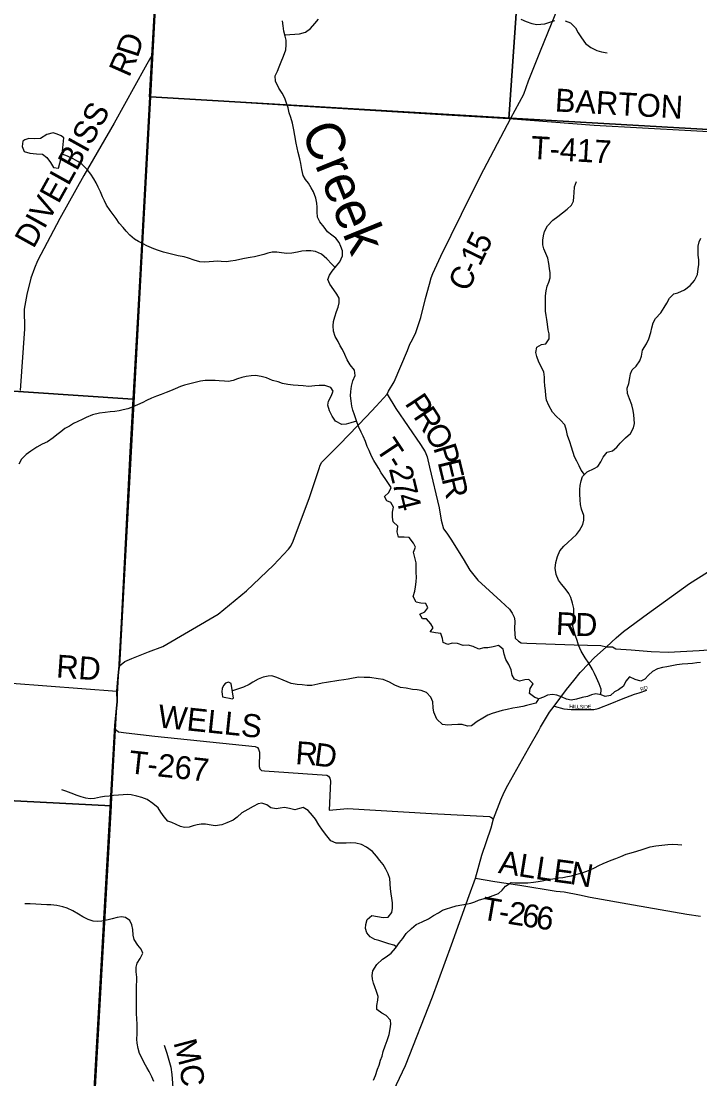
# Model space of a CAD drawing. Extents: x 1759416 to 2214760, y 252598 to 1116833.
# Drawn here: x 1977423 to 1986288, y 885483 to 899295 of the extents above; entities that cross this region are included whole.
import ezdxf

# ---------------------------------------------------------------- set-up
doc = ezdxf.new("R2010")
doc.units = 0
for name, color, linetype in [('GM_X_County_Road', 7, 'Continuous'), ('GM_X_County_Road_Text', 7, 'Continuous'), ('GM_X_Minor_Lake', 7, 'Continuous'), ('GM_X_Minor_River', 7, 'Continuous'), ('GM_X_Minor_River_Text', 7, 'Continuous'), ('GM_X_Section', 7, 'Continuous'), ('GM_X_State_Route', 7, 'Continuous'), ('GM_X_Township', 7, 'Continuous'), ('GM_X_Township_Road', 7, 'Continuous'), ('GM_X_Township_Road_Text', 7, 'Continuous'), ('GM_X_Township_Subdivision', 7, 'Continuous'), ('GM_X_Township_Subdivision_Text', 7, 'Continuous')]:
    doc.layers.add(name, color=color, linetype=linetype)

msp = doc.modelspace()

# ---------------------------------------------------------------- linework, layer by layer
at = {"layer": 'GM_X_County_Road'}
for points in [[(1983819, 898028), (1983988, 898340), (1984048, 898516), (1984207, 898906), (1984400, 899379), (1984779, 900247), (1984893, 900512), (1984969, 900674)], [(1978703, 890857), (1978707, 890875), (1978778, 890932), (1978869, 890972), (1979088, 891058), (1979274, 891129), (1979996, 891552), (1980365, 891854), (1980721, 892190), (1980914, 892400), (1980948, 892438), (1980976, 892505), (1981189, 893075), (1981315, 893454), (1981329, 893498), (1981351, 893534), (1981584, 893772), (1981932, 894130), (1982061, 894266), (1982203, 894422), (1982221, 894462), (1982297, 894586), (1982468, 894993), (1982502, 895077), (1982536, 895137), (1982578, 895229), (1982642, 895423), (1982706, 895671), (1982757, 895859), (1982779, 895944), (1982799, 896000), (1982905, 896226), (1983174, 896776), (1983425, 897273), (1983819, 898028)], [(1972514, 887236), (1972538, 887251), (1972709, 887356), (1973825, 888105), (1974073, 888287), (1974650, 888727), (1975449, 889323), (1976258, 889912), (1976731, 890268), (1976773, 890314), (1976797, 890358), (1976815, 890434), (1976839, 890684), (1978673, 890545), (1978688, 890708), (1978698, 890834), (1978703, 890857)]]:
    msp.add_lwpolyline(points, dxfattribs=at)
at = {"layer": 'GM_X_Minor_Lake'}
for points in [[(1977983, 897770), (1977947, 897796), (1977895, 897821), (1977843, 897837), (1977759, 897815), (1977674, 897764), (1977598, 897760), (1977524, 897761), (1977470, 897747), (1977444, 897727), (1977436, 897657), (1977463, 897593), (1977535, 897570), (1977623, 897564), (1977701, 897557), (1977761, 897515), (1977805, 897451), (1977844, 897382), (1977910, 897374)], [(1977910, 897374), (1977959, 897552), (1977983, 897770)], [(1980168, 890646), (1980130, 890662), (1980094, 890649), (1980068, 890619), (1980049, 890581), (1980045, 890535), (1980047, 890505), (1980053, 890473), (1980099, 890464), (1980145, 890454), (1980179, 890446), (1980199, 890456)], [(1980199, 890456), (1980168, 890646)]]:
    msp.add_lwpolyline(points, dxfattribs=at)
at = {"layer": 'GM_X_Minor_River'}
for points in [[(1980866, 899117), (1980996, 899123), (1981060, 899131), (1981139, 899152), (1981203, 899198), (1981261, 899263), (1981308, 899321)], [(1982289, 892946), (1982253, 893007), (1982199, 893031), (1982171, 893089), (1982224, 893139), (1982258, 893203), (1982213, 893270), (1982177, 893322), (1982127, 893398), (1982096, 893453), (1982066, 893503), (1982032, 893557), (1981998, 893615), (1981967, 893690), (1981945, 893742), (1981922, 893804), (1981892, 893875), (1981864, 893929), (1981835, 893993), (1981811, 894049), (1981793, 894100), (1981776, 894152), (1981756, 894214), (1981744, 894268), (1981733, 894338), (1981727, 894400), (1981728, 894459), (1981738, 894527), (1981754, 894597), (1981787, 894667), (1981779, 894735), (1981720, 894805), (1981680, 894872), (1981653, 894940), (1981619, 895006), (1981591, 895056), (1981564, 895111), (1981526, 895177), (1981504, 895245), (1981499, 895315), (1981505, 895372), (1981520, 895432), (1981544, 895503), (1981564, 895561), (1981577, 895615), (1981575, 895678), (1981545, 895728), (1981506, 895788), (1981454, 895859), (1981431, 895921), (1981453, 895977), (1981485, 896031), (1981544, 896100), (1981586, 896152), (1981621, 896230), (1981619, 896296), (1981601, 896353), (1981576, 896405), (1981532, 896459), (1981480, 896498), (1981426, 896542), (1981381, 896606), (1981323, 896673), (1981296, 896735), (1981290, 896803), (1981288, 896865), (1981285, 896919), (1981271, 896982), (1981240, 897068), (1981210, 897120), (1981176, 897177), (1981138, 897229), (1981107, 897279), (1981091, 897357), (1981078, 897434), (1981064, 897496), (1981043, 897578), (1981029, 897640), (1981015, 897700), (1980998, 897801), (1980984, 897875), (1980967, 897961), (1980945, 898037), (1980926, 898098), (1980910, 898162), (1980894, 898212), (1980869, 898288), (1980831, 898355), (1980790, 898421), (1980744, 898512), (1980743, 898582), (1980773, 898640), (1980793, 898698), (1980820, 898763), (1980848, 898837), (1980879, 898921), (1980887, 898985), (1980884, 899048), (1980870, 899098), (1980856, 899162), (1980847, 899232)], [(1980847, 899232), (1980837, 899300)], [(1983950, 899320), (1984020, 899292), (1984094, 899263), (1984160, 899253), (1984210, 899255), (1984264, 899262), (1984341, 899286), (1984393, 899302)], [(1984529, 899301), (1984597, 899274), (1984664, 899208), (1984700, 899141), (1984742, 899077), (1984795, 899004), (1984863, 898950), (1984943, 898913), (1985005, 898893), (1985077, 898882)], [(1981525, 896078), (1981482, 896123), (1981418, 896189), (1981347, 896252), (1981267, 896285), (1981209, 896297), (1981147, 896295), (1981091, 896290), (1981034, 896278), (1980960, 896266), (1980894, 896261), (1980826, 896269), (1980764, 896280), (1980704, 896280), (1980646, 896264), (1980592, 896249), (1980471, 896218), (1980413, 896210), (1980341, 896196), (1980281, 896183), (1980225, 896171), (1980157, 896159), (1980105, 896154), (1980037, 896156), (1979985, 896159), (1979935, 896157), (1979880, 896153), (1979820, 896148), (1979758, 896150), (1979684, 896172), (1979610, 896199), (1979551, 896217), (1979473, 896232), (1979403, 896246), (1979351, 896259), (1979281, 896279), (1979219, 896300), (1979155, 896322), (1979067, 896359), (1979015, 896385), (1978957, 896418), (1978903, 896448), (1978844, 896500), (1978796, 896551), (1978754, 896601), (1978705, 896658), (1978663, 896718), (1978625, 896772), (1978587, 896823), (1978540, 896893), (1978512, 896947), (1978488, 896999), (1978459, 897068), (1978429, 897126), (1978402, 897182), (1978372, 897235), (1978334, 897297), (1978285, 897359), (1978217, 897426), (1978165, 897460), (1978101, 897499), (1978027, 897531), (1977960, 897556)], [(1984782, 893374), (1984738, 893432), (1984710, 893488), (1984681, 893550), (1984651, 893604), (1984610, 893731), (1984592, 893801), (1984559, 893886), (1984545, 893950), (1984524, 894022), (1984468, 894084), (1984410, 894137), (1984364, 894189), (1984317, 894274), (1984287, 894346), (1984278, 894408), (1984272, 894472), (1984262, 894532), (1984257, 894595), (1984257, 894647), (1984250, 894715), (1984186, 894843), (1984161, 894916), (1984145, 894970), (1984160, 895038), (1984222, 895074), (1984278, 895083), (1984318, 895147), (1984321, 895211), (1984309, 895265), (1984300, 895340), (1984290, 895400), (1984280, 895450), (1984273, 895506), (1984271, 895564), (1984270, 895644), (1984270, 895708), (1984280, 895772), (1984295, 895832), (1984317, 895888), (1984331, 895944), (1984332, 896008), (1984326, 896065), (1984317, 896131), (1984303, 896199), (1984275, 896259), (1984252, 896320), (1984238, 896372), (1984239, 896434), (1984247, 896492), (1984261, 896550), (1984298, 896622), (1984368, 896695), (1984433, 896743), (1984493, 896793), (1984555, 896838), (1984612, 896890), (1984636, 896944), (1984642, 897002), (1984645, 897054), (1984653, 897130), (1984678, 897200)], [(1984996, 890498), (1985000, 890573), (1984971, 890642), (1984939, 890720), (1984913, 890774), (1984888, 890830), (1984838, 890911), (1984791, 890981), (1984739, 891066), (1984705, 891144), (1984686, 891206), (1984662, 891269), (1984647, 891323), (1984633, 891373), (1984627, 891439), (1984636, 891491), (1984642, 891545), (1984642, 891625), (1984625, 891694), (1984601, 891768), (1984576, 891820), (1984528, 891884), (1984480, 891943), (1984441, 891993), (1984413, 892069), (1984400, 892152), (1984406, 892226), (1984431, 892304), (1984459, 892376), (1984511, 892437), (1984566, 892487), (1984622, 892541), (1984679, 892593), (1984715, 892644), (1984758, 892722), (1984772, 892780), (1984772, 892838), (1984743, 892921), (1984729, 892985), (1984724, 893043), (1984720, 893119), (1984720, 893177), (1984725, 893233), (1984737, 893291), (1984755, 893347), (1984818, 893411), (1984906, 893455), (1984957, 893480), (1984997, 893540), (1985025, 893602), (1985078, 893668), (1985146, 893685), (1985204, 893731), (1985249, 893783), (1985319, 893853), (1985382, 893910), (1985422, 893986), (1985433, 894040), (1985429, 894098), (1985427, 894156), (1985416, 894211), (1985398, 894285), (1985371, 894363), (1985343, 894433), (1985339, 894504), (1985362, 894562), (1985374, 894636), (1985381, 894690), (1985405, 894742), (1985455, 894789), (1985504, 894857), (1985524, 894919), (1985541, 894997), (1985591, 895079), (1985624, 895147), (1985650, 895229), (1985661, 895291), (1985679, 895357), (1985707, 895413), (1985778, 895486), (1985822, 895554), (1985859, 895614), (1985893, 895676), (1985950, 895732), (1986002, 895749), (1986086, 895785), (1986161, 895841), (1986217, 895910), (1986258, 895986), (1986268, 896060), (1986275, 896118), (1986275, 896180), (1986265, 896240), (1986268, 896297), (1986268, 896357), (1986280, 896411), (1986303, 896463)], [(1981803, 894073), (1981729, 894050), (1981667, 894032), (1981611, 894029), (1981529, 894073), (1981485, 894138), (1981452, 894204), (1981430, 894278), (1981440, 894334), (1981473, 894396), (1981497, 894462), (1981470, 894512), (1981390, 894537), (1981318, 894539), (1981258, 894534), (1981179, 894524), (1981107, 894531), (1981043, 894535), (1980975, 894542), (1980907, 894550), (1980837, 894564), (1980781, 894583), (1980707, 894603), (1980630, 894636), (1980558, 894654), (1980486, 894669), (1980426, 894665), (1980363, 894656), (1980305, 894640), (1980251, 894622), (1980193, 894603), (1980133, 894591), (1980079, 894595), (1980011, 894600), (1979959, 894604), (1979901, 894604), (1979825, 894603), (1979767, 894595), (1979680, 894570), (1979608, 894556), (1979558, 894543), (1979506, 894523), (1979434, 894493), (1979373, 894468), (1979317, 894446), (1979253, 894420), (1979193, 894397), (1979126, 894371), (1979062, 894341), (1979012, 894316), (1978944, 894284), (1978873, 894254), (1978815, 894231), (1978757, 894217), (1978705, 894205), (1978649, 894198), (1978587, 894192), (1978519, 894185), (1978447, 894177), (1978354, 894152), (1978274, 894120), (1978220, 894094), (1978162, 894067), (1978107, 894039), (1978055, 894005), (1977995, 893974), (1977943, 893934), (1977890, 893892), (1977840, 893852), (1977766, 893803), (1977697, 893769), (1977629, 893730), (1977549, 893680), (1977488, 893636), (1977428, 893577), (1977393, 893511)], [(1986298, 890918), (1986248, 890914), (1986191, 890908), (1986131, 890903), (1986059, 890897), (1985989, 890887), (1985923, 890878), (1985855, 890864), (1985799, 890855), (1985733, 890835), (1985668, 890801), (1985618, 890754), (1985570, 890702), (1985517, 890676), (1985445, 890699), (1985368, 890731), (1985323, 890677), (1985293, 890609), (1985224, 890564), (1985174, 890536), (1985120, 890488), (1985052, 890475), (1984998, 890497), (1984930, 890512), (1984872, 890498), (1984819, 890474), (1984751, 890461), (1984675, 890439), (1984609, 890426), (1984545, 890440), (1984489, 890468), (1984419, 890493), (1984365, 890503), (1984297, 890492), (1984247, 890466), (1984187, 890444), (1984133, 890461), (1984063, 890513), (1984073, 890579), (1984110, 890643), (1984054, 890696), (1984002, 890692), (1983932, 890676), (1983866, 890701), (1983838, 890753), (1983823, 890825), (1983793, 890893), (1983755, 890960), (1983732, 891030), (1983718, 891092), (1983658, 891141), (1983590, 891125), (1983518, 891112), (1983468, 891112), (1983402, 891092), (1983326, 891129), (1983264, 891145), (1983196, 891140), (1983122, 891166), (1983054, 891171), (1982998, 891153), (1982934, 891181), (1982926, 891234), (1982905, 891300), (1982835, 891306), (1982767, 891319), (1982807, 891373), (1982775, 891425), (1982716, 891489), (1982666, 891488), (1982630, 891552), (1982696, 891582), (1982737, 891635), (1982707, 891692), (1982645, 891694), (1982581, 891707), (1982545, 891781), (1982564, 891853), (1982576, 891907), (1982583, 891975), (1982587, 892033), (1982585, 892093), (1982584, 892149), (1982582, 892219), (1982565, 892290), (1982547, 892362), (1982576, 892426), (1982548, 892480), (1982492, 892551), (1982424, 892555), (1982354, 892557), (1982333, 892626), (1982345, 892698), (1982283, 892756), (1982274, 892818), (1982274, 892882), (1982289, 892946)], [(1984179, 890446), (1984144, 890390), (1984092, 890377), (1984026, 890359), (1983974, 890347), (1983904, 890330), (1983847, 890322), (1983773, 890307), (1983705, 890293), (1983575, 890254), (1983521, 890232), (1983452, 890193), (1983380, 890147), (1983307, 890091), (1983255, 890090), (1983183, 890110), (1983125, 890110), (1983049, 890105), (1982997, 890101), (1982925, 890110), (1982852, 890178), (1982814, 890271), (1982804, 890327), (1982799, 890405), (1982775, 890467), (1982718, 890530), (1982648, 890554), (1982596, 890563), (1982534, 890569), (1982452, 890584), (1982380, 890594), (1982304, 890625), (1982236, 890661), (1982150, 890696), (1982086, 890706), (1981978, 890723), (1981902, 890725), (1981832, 890726), (1981760, 890714), (1981696, 890703), (1981636, 890693), (1981572, 890683), (1981519, 890676), (1981463, 890668), (1981411, 890658), (1981355, 890649), (1981299, 890635), (1981219, 890621), (1981161, 890620), (1981093, 890626), (1981027, 890631), (1980951, 890647), (1980897, 890666), (1980845, 890688), (1980763, 890723), (1980699, 890745), (1980649, 890741), (1980583, 890728), (1980521, 890700), (1980450, 890662), (1980400, 890633), (1980326, 890599), (1980264, 890576), (1980184, 890548)], [(1982327, 887208), (1982290, 887229), (1982226, 887245), (1982160, 887268), (1982097, 887288), (1982045, 887303), (1981983, 887339), (1981939, 887390), (1981923, 887448), (1981926, 887498), (1981942, 887562), (1982005, 887614), (1982079, 887603), (1982151, 887589), (1982215, 887592), (1982263, 887654), (1982273, 887710), (1982272, 887780), (1982264, 887840), (1982255, 887900), (1982249, 887963), (1982238, 888099), (1982216, 888159), (1982187, 888221), (1982153, 888280), (1982107, 888334), (1982066, 888390), (1982012, 888451), (1981932, 888509), (1981868, 888544), (1981796, 888562), (1981722, 888563), (1981668, 888559), (1981608, 888560), (1981536, 888562), (1981468, 888589), (1981417, 888655), (1981361, 888729), (1981311, 888798), (1981266, 888872), (1981230, 888923), (1981174, 888989), (1981109, 889026), (1981058, 889014), (1980996, 888994), (1980928, 889013), (1980864, 889025), (1980806, 889017), (1980756, 889008), (1980686, 889022), (1980634, 889061), (1980568, 889081), (1980518, 889073), (1980452, 889038), (1980386, 889000), (1980307, 888957), (1980243, 888901), (1980193, 888861), (1980110, 888826), (1980044, 888800), (1979958, 888786), (1979904, 888795), (1979832, 888807), (1979776, 888810), (1979722, 888800), (1979670, 888786), (1979618, 888769), (1979557, 888763), (1979506, 888779), (1979450, 888804), (1979392, 888830), (1979340, 888849), (1979292, 888905), (1979248, 888963), (1979211, 889020), (1979145, 889080), (1979069, 889129), (1978999, 889155), (1978933, 889172), (1978859, 889190), (1978807, 889195), (1978755, 889193), (1978697, 889189), (1978629, 889182), (1978571, 889176), (1978511, 889168), (1978459, 889159), (1978383, 889145), (1978325, 889140), (1978267, 889148), (1978209, 889164), (1978157, 889183), (1978077, 889213), (1978005, 889240), (1977953, 889258)], [(1985132, 888339), (1985192, 888362), (1985255, 888384), (1985325, 888416), (1985393, 888435), (1985467, 888457), (1985533, 888476), (1985588, 888496), (1985638, 888512), (1985714, 888525), (1985792, 888535), (1985870, 888542), (1985932, 888546), (1986000, 888544), (1986052, 888539)], [(1982027, 885464), (1982053, 885526), (1982080, 885608), (1982100, 885660), (1982117, 885726), (1982137, 885778), (1982153, 885838), (1982180, 885914), (1982204, 885984), (1982229, 886062), (1982245, 886136), (1982252, 886196), (1982248, 886248), (1982190, 886310), (1982135, 886339), (1982067, 886387), (1982067, 886441), (1982082, 886509), (1982086, 886559), (1982066, 886625), (1982041, 886682), (1982027, 886734), (1982013, 886784), (1982008, 886834), (1982016, 886892), (1982069, 886974), (1982141, 887044), (1982191, 887077), (1982258, 887125), (1982314, 887191), (1982367, 887263), (1982407, 887316), (1982451, 887380), (1982520, 887444), (1982582, 887496), (1982661, 887535), (1982743, 887573), (1982809, 887616), (1982874, 887652), (1982926, 887686), (1982978, 887701), (1983034, 887719), (1983106, 887741), (1983179, 887756), (1983231, 887764), (1983295, 887778), (1983347, 887793), (1983399, 887817), (1983469, 887837), (1983521, 887850), (1983658, 887905), (1983708, 887947), (1983751, 887999), (1983823, 888045), (1983873, 888044), (1983927, 888042), (1983989, 888042), (1984041, 888043), (1984115, 888049), (1984175, 888060), (1984230, 888070), (1984312, 888084), (1984396, 888097), (1984448, 888107), (1984498, 888112), (1984558, 888124), (1984612, 888134), (1984666, 888151), (1984751, 888175), (1984801, 888191), (1984855, 888212), (1984911, 888238), (1984968, 888268), (1985024, 888293), (1985078, 888317), (1985132, 888339)], [(1978735, 887598), (1978677, 887591), (1978613, 887573), (1978561, 887559), (1978479, 887542), (1978427, 887536), (1978365, 887541), (1978297, 887563), (1978227, 887600), (1978171, 887632), (1978097, 887675), (1978023, 887713), (1977969, 887731), (1977889, 887746), (1977813, 887754), (1977759, 887757), (1977683, 887759), (1977615, 887764), (1977543, 887766), (1977473, 887769)], [(1979156, 885450), (1979130, 885510), (1979095, 885577), (1979067, 885629), (1979030, 885693), (1978994, 885764), (1978968, 885814), (1978951, 885878), (1978937, 885948), (1978933, 886000), (1978940, 886071), (1978940, 886139), (1978939, 886195), (1978935, 886267), (1978930, 886337), (1978928, 886407), (1978928, 886463), (1978931, 886513), (1978929, 886595), (1978932, 886656), (1978932, 886706), (1978934, 886756), (1978933, 886812), (1978927, 886882), (1978925, 886942), (1978940, 886994), (1978976, 887052), (1979011, 887124), (1978991, 887178), (1978949, 887230), (1978900, 887301), (1978886, 887361), (1978880, 887431), (1978867, 887495), (1978841, 887552), (1978787, 887588), (1978735, 887598)]]:
    msp.add_lwpolyline(points, dxfattribs=at)
at = {"layer": 'GM_X_Section'}
for points in [[(1984176, 903528), (1983794, 898018), (1982978, 898066), (1981055, 898186), (1979098, 898305), (1979185, 899839), (1979392, 903857)], [(1989634, 903190), (1989270, 897688), (1988740, 897714), (1986801, 897826), (1984910, 897934), (1983794, 898018), (1984176, 903528)], [(1979185, 899839), (1979098, 898305), (1978969, 895901), (1978883, 894359), (1973427, 894726), (1973703, 900155)], [(1978883, 894359), (1978845, 893672), (1978729, 891445), (1978603, 889173), (1978599, 889048), (1973201, 889326), (1973427, 894726)], [(1973201, 889326), (1978599, 889048), (1978479, 886916), (1978370, 884986), (1978281, 883552), (1972879, 883916)]]:
    msp.add_lwpolyline(points, close=True, dxfattribs=at)
at = {"layer": 'GM_X_State_Route'}
for points in [[(1985070, 891125), (1985197, 891242), (1985292, 891324), (1985603, 891553), (1986152, 891953), (1986507, 892172)], [(1984189, 890041), (1984208, 890075), (1984324, 890269), (1984386, 890349), (1984546, 890566), (1984641, 890686), (1984726, 890790), (1984838, 890905), (1984910, 890981), (1985070, 891125)], [(1981096, 883453), (1981250, 883656), (1981572, 884101), (1981789, 884419), (1981995, 884755), (1982009, 884782), (1982163, 885071), (1982443, 885656), (1982796, 886554), (1983044, 887232), (1983277, 887878), (1983358, 888104), (1983440, 888403), (1983564, 888762), (1983595, 888877), (1983687, 889125), (1983733, 889226), (1983782, 889319), (1984056, 889807), (1984189, 890041)]]:
    msp.add_lwpolyline(points, dxfattribs=at)
at = {"layer": 'GM_X_Township'}
for points in [[(1999329, 897063), (1998108, 897126), (1994987, 897287), (1993785, 897363), (1989453, 897682), (1987762, 897801), (1983819, 898028), (1979115, 898305), (1979144, 898890), (1979148, 898965), (1979181, 899629), (1979253, 901083), (1979280, 901405), (1979291, 901555), (1979302, 901673), (1979490, 905682), (1979566, 907131), (1979748, 910072), (1979980, 914711), (1980054, 916429)], [(1975033, 905927), (1979490, 905682), (1979302, 901673), (1979291, 901555), (1979280, 901405), (1979253, 901083), (1979181, 899629), (1979148, 898965), (1979144, 898890), (1979115, 898305), (1978707, 890875), (1978698, 890834), (1978688, 890708), (1978673, 890545), (1978676, 890411), (1978648, 890099), (1978275, 883589)], [(1978275, 883589), (1978648, 890099), (1978676, 890411), (1978673, 890545), (1978688, 890708), (1978698, 890834), (1978707, 890875), (1979115, 898305), (1983819, 898028), (1987762, 897801), (1989453, 897682), (1993785, 897363), (1994987, 897287), (1998108, 897126), (1999329, 897063)]]:
    msp.add_lwpolyline(points, dxfattribs=at)
at = {"layer": 'GM_X_Township_Road'}
for points in [[(1979253, 901083), (1979253, 901083), (1979181, 899629), (1979148, 898965), (1979144, 898890), (1979121, 898828), (1979106, 898801)], [(1979106, 898801), (1979045, 898692), (1978637, 897961), (1978241, 897280), (1977928, 896719), (1977638, 896164), (1977598, 896068), (1977551, 895940), (1977496, 895726), (1977463, 895534), (1977468, 895279), (1977411, 894470)], [(1983819, 898028), (1987762, 897801)], [(1982203, 894422), (1982319, 894238), (1982640, 893767), (1982672, 893719), (1982700, 893671), (1982725, 893604), (1982759, 893470), (1982883, 892938), (1982908, 892778), (1982939, 892665), (1982984, 892608), (1983035, 892531), (1983198, 892272), (1983283, 892127), (1983388, 891993), (1983690, 891721), (1983801, 891614), (1983837, 891563), (1983863, 891511), (1983872, 891465), (1983869, 891355), (1983878, 891238), (1983920, 891198), (1983956, 891178), (1984027, 891174), (1984648, 891151), (1984993, 891141), (1985070, 891125)], [(1985070, 891125), (1985147, 891124), (1985192, 891100), (1985392, 891084), (1985651, 891065), (1985873, 891055), (1986278, 891075), (1986468, 891088)], [(1978673, 890545), (1978676, 890411), (1978648, 890099), (1978657, 890044), (1978667, 890036)], [(1978667, 890036), (1978693, 890015), (1978793, 889999), (1979171, 889956), (1980479, 889822), (1980509, 889808), (1980525, 889787), (1980537, 889749), (1980532, 889561), (1980542, 889533), (1980562, 889511), (1980600, 889503), (1981414, 889448), (1981438, 889436), (1981456, 889408), (1981464, 889370), (1981445, 888991), (1981688, 889011), (1982781, 888949), (1983541, 888908), (1983560, 888901), (1983595, 888877)], [(1983358, 888104), (1983609, 888058), (1983936, 888010), (1984410, 887932), (1984517, 887923), (1984715, 887884), (1984857, 887857), (1985423, 887755), (1986118, 887633), (1986295, 887609)], [(1979291, 885921), (1979325, 885819), (1979378, 885634), (1979393, 885538), (1979408, 885308), (1979410, 884961), (1979418, 884931), (1979446, 884901), (1979508, 884885), (1980408, 884868), (1981391, 884806), (1981866, 884762), (1981995, 884755)]]:
    msp.add_lwpolyline(points, dxfattribs=at)
at = {"layer": 'GM_X_Township_Subdivision'}
for points in [[(1984386, 890349), (1984511, 890313), (1984607, 890308), (1984818, 890305), (1984903, 890308), (1984959, 890319), (1985140, 890388), (1985265, 890439), (1985436, 890505), (1985497, 890525)], [(1985497, 890525), (1985597, 890558)]]:
    msp.add_lwpolyline(points, dxfattribs=at)

# ---------------------------------------------------------------- texts
at = {"layer": 'GM_X_County_Road_Text'}
for s, rotation, p in [('5', 63.9214, (1983495, 896247)), ('1', 64.2239, (1983415, 896081)), ('C', 65.7867, (1983262, 895747)), ('-', 64.7685, (1983363, 895970)), ('RD', 356.0551, (1977875, 890724))]:
    msp.add_text(s, height=300, rotation=rotation, dxfattribs=at).set_placement(p)
at = {"layer": 'GM_X_Minor_River_Text'}
msp.add_text('Creek', height=500.1, rotation=291.9468, dxfattribs=at).set_placement((1981076, 897869))
at = {"layer": 'GM_X_Township_Road_Text'}
for s, rotation, p in [('D', 71.9039, (1978945, 898806)), ('R', 66.0209, (1978833, 898550)), ('BARTON', 356.6531, (1984390, 898117)), ('DIVELBISS', 60.9074, (1977585, 896314)), ('T-417', 356.6343, (1984075, 897497)), ('P', 303.4555, (1982427, 894303)), ('R', 303.4411, (1982538, 894134)), ('O', 301.6922, (1982673, 893931)), ('T', 303.7614, (1982046, 893718)), ('P', 287.1307, (1982803, 893724)), ('-', 302.0294, (1982169, 893534)), ('E', 283.6018, (1982861, 893536)), ('2', 284.0501, (1982225, 893452)), ('7', 283.7182, (1982270, 893273)), ('R', 283.4995, (1982914, 893318)), ('4', 283.6967, (1982313, 893094)), ('R', 357.345, (1984403, 891280)), ('D', 358.7562, (1984657, 891268)), ('WELLS', 354.0226, (1979199, 890074)), ('R', 355.7926, (1980999, 889594)), ('D', 352.4304, (1981240, 889577)), ('T-267', 353.8131, (1978817, 889475)), ('A', 350.8653, (1983647, 888173)), ('L', 350.9472, (1983908, 888131)), ('L', 351.0946, (1984131, 888095)), ('E', 352.3434, (1984360, 888059)), ('N', 350.0047, (1984579, 888030)), ('T', 350.1023, (1983421, 887568)), ('2', 351.1865, (1983769, 887509)), ('6', 351.2352, (1983952, 887480)), ('6', 351.2533, (1984135, 887452)), ('-', 351.0135, (1983647, 887528)), ('M', 284.8787, (1979411, 885958)), ('C', 276.866, (1979492, 885654))]:
    msp.add_text(s, height=300, rotation=rotation, dxfattribs=at).set_placement(p)
at = {"layer": 'GM_X_Township_Subdivision_Text'}
for s, rotation, p in [('RD', 19.4434, (1985520, 890542)), ('H', 357.9234, (1984582, 890322)), ('I', 357.9016, (1984625, 890321)), ('L', 357.9332, (1984648, 890320)), ('L', 357.9234, (1984683, 890319)), ('S', 357.9194, (1984718, 890317)), ('I', 357.9016, (1984753, 890316)), ('D', 359.182, (1984776, 890315)), ('E', 4.2059, (1984825, 890315))]:
    msp.add_text(s, height=50, rotation=rotation, dxfattribs=at).set_placement(p)

doc.saveas('drawing.dxf')
